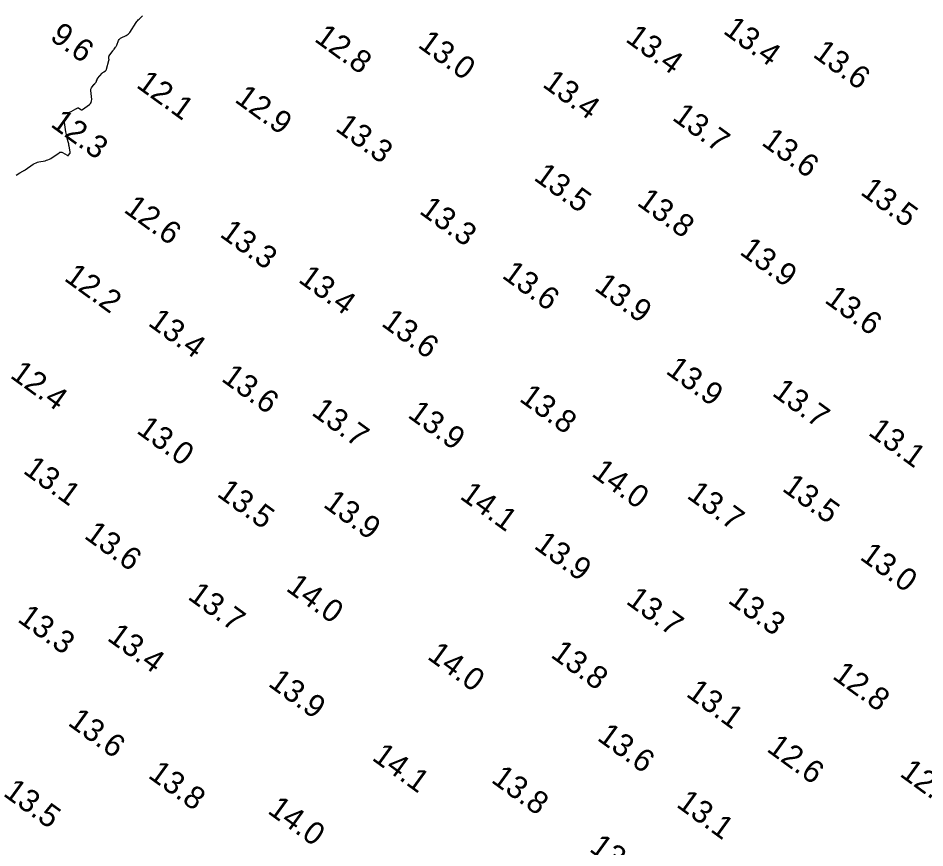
# Model space of a CAD drawing. Extents: x 815352 to 820877, y 582403 to 597439.
# Drawn here: x 817656.6 to 817857, y 585609.5 to 585793 of the extents above; entities that cross this region are included whole.
import ezdxf

# ---------------------------------------------------------------- set-up
doc = ezdxf.new("R2010")
doc.units = 0
doc.layers.add('V-CONT-EL12', color=7, linetype='Continuous')
doc.layers.add('V-TOPO-SOUN', color=7, linetype='Continuous')

msp = doc.modelspace()

# ---------------------------------------------------------------- linework, layer by layer
at = {"layer": 'V-CONT-EL12'}
msp.add_lwpolyline([(817656.1, 585758.28), (817656.92, 585758.79), (817657.02, 585758.85), (817657.12, 585758.91), (817657.22, 585758.97), (817657.32, 585759.03), (817657.73, 585759.25), (817657.83, 585759.31), (817657.94, 585759.37), (817658.03, 585759.44), (817658.13, 585759.5), (817659.93, 585760.73), (817660.22, 585760.91), (817660.53, 585761.06), (817660.84, 585761.17), (817661.17, 585761.25), (817662.52, 585761.51), (817662.85, 585761.59), (817663.17, 585761.7), (817663.48, 585761.84), (817663.77, 585762.02), (817665.63, 585763.27), (817665.82, 585763.37), (817666.02, 585763.41), (817666.21, 585763.38), (817666.41, 585763.29), (817667.44, 585762.7), (817667.52, 585762.66), (817667.6, 585762.66), (817667.68, 585762.69), (817667.74, 585762.76), (817668, 585763.08), (817668.05, 585763.17), (817668.08, 585763.26), (817668.1, 585763.36), (817668.09, 585763.46), (817667.86, 585764.72), (817667.81, 585764.96), (817667.76, 585765.21), (817667.7, 585765.45), (817667.64, 585765.69), (817667.36, 585766.79), (817667.29, 585767.06), (817667.23, 585767.32), (817667.18, 585767.59), (817667.14, 585767.86), (817666.82, 585769.95), (817666.8, 585770.21), (817666.83, 585770.45), (817666.91, 585770.69), (817667.03, 585770.91), (817667.68, 585771.88), (817667.8, 585772.04), (817667.94, 585772.18), (817668.1, 585772.31), (817668.27, 585772.41), (817669.33, 585772.98), (817669.34, 585772.98), (817669.35, 585772.99), (817669.36, 585773), (817669.38, 585773.01), (817669.42, 585773.04), (817669.43, 585773.05), (817669.44, 585773.06), (817669.45, 585773.07), (817669.46, 585773.07), (817669.74, 585773.18), (817669.79, 585773.19), (817669.84, 585773.19), (817669.89, 585773.18), (817669.94, 585773.16), (817670.42, 585772.81), (817670.52, 585772.76), (817670.61, 585772.74), (817670.71, 585772.76), (817670.8, 585772.81), (817672.33, 585773.92), (817672.58, 585774.15), (817672.74, 585774.41), (817672.82, 585774.71), (817672.83, 585775.05), (817672.62, 585777), (817672.62, 585777.18), (817672.65, 585777.34), (817672.71, 585777.5), (817672.81, 585777.65), (817673.41, 585778.4), (817673.46, 585778.46), (817673.5, 585778.52), (817673.55, 585778.58), (817673.6, 585778.64), (817673.79, 585778.89), (817673.83, 585778.95), (817673.87, 585779.01), (817673.9, 585779.07), (817673.93, 585779.14), (817674.01, 585779.41), (817674.04, 585779.47), (817674.07, 585779.54), (817674.11, 585779.6), (817674.15, 585779.65), (817675.18, 585780.87), (817675.25, 585780.95), (817675.33, 585781.03), (817675.42, 585781.1), (817675.51, 585781.17), (817675.87, 585781.41), (817675.96, 585781.48), (817676.03, 585781.56), (817676.08, 585781.65), (817676.11, 585781.75), (817676.62, 585783.63), (817676.64, 585783.72), (817676.66, 585783.81), (817676.66, 585783.9), (817676.65, 585783.99), (817676.62, 585784.35), (817676.62, 585784.44), (817676.63, 585784.52), (817676.66, 585784.6), (817676.71, 585784.68), (817677.5, 585785.78), (817677.58, 585785.89), (817677.65, 585785.99), (817677.73, 585786.09), (817677.81, 585786.19), (817678.12, 585786.59), (817678.2, 585786.69), (817678.26, 585786.8), (817678.32, 585786.91), (817678.38, 585787.03), (817678.79, 585788.07), (817678.89, 585788.27), (817679.03, 585788.44), (817679.19, 585788.58), (817679.38, 585788.69), (817680.47, 585789.2), (817680.71, 585789.33), (817680.92, 585789.49), (817681.11, 585789.68), (817681.27, 585789.89), (817682.67, 585792.05), (817682.81, 585792.25), (817682.96, 585792.45), (817683.12, 585792.63), (817683.3, 585792.8), (817684.06, 585793.51)], dxfattribs=at)

# ---------------------------------------------------------------- texts
at = {"layer": 'V-TOPO-SOUN'}
for s, p in [('9.6', (817663.38, 585788.41)), ('12.8 ', (817721.83, 585788.1)), ('13.4 ', (817812.22, 585789.84)), ('13.0 ', (817744.73, 585786.77)), ('13.4 ', (817790.63, 585788.03)), ('13.6 ', (817832.04, 585784.65)), ('13.4 ', (817772.26, 585778.03)), ('12.1 ', (817682.48, 585777.89)), ('12.9 ', (817704.21, 585774.68)), ('13.7 ', (817800.96, 585770.68)), ('12.3 ', (817663.53, 585769.24)), ('13.3 ', (817726.49, 585768.32)), ('13.6 ', (817820.69, 585765.16)), ('13.5 ', (817770.34, 585757.42)), ('13.5 ', (817842.55, 585754.21)), ('12.6 ', (817679.71, 585750.3)), ('13.3 ', (817745.03, 585750.01)), ('13.8 ', (817793.16, 585751.85)), ('13.3 ', (817700.93, 585744.89)), ('13.9 ', (817815.86, 585740.99)), ('12.2 ', (817666.52, 585735.18)), ('13.4 ', (817718.29, 585734.85)), ('13.6 ', (817763.31, 585735.77)), ('13.9 ', (817783.74, 585733.05)), ('13.6 ', (817834.63, 585730.32)), ('13.4 ', (817685.08, 585725.24)), ('13.6 ', (817736.64, 585725.17)), ('13.9 ', (817799.52, 585714.64)), ('12.4 ', (817654.57, 585713.69)), ('13.6 ', (817701.27, 585712.96)), ('13.8 ', (817767.14, 585708.51)), ('13.7 ', (817823.04, 585709.75)), ('13.7 ', (817721.21, 585705.46)), ('13.9 ', (817742.47, 585704.93)), ('13.0 ', (817682.53, 585701.46)), ('13.1 ', (817844.29, 585701.02)), ('13.1 ', (817657.45, 585692.59)), ('14.0 ', (817783.12, 585691.95)), ('13.5 ', (817825.26, 585688.66)), ('13.5 ', (817700.3, 585687.48)), ('14.1 ', (817754, 585686.94)), ('13.7 ', (817804.18, 585687.08)), ('13.9 ', (817723.8, 585685.11)), ('13.6 ', (817670.95, 585678.19)), ('13.9 ', (817770.39, 585675.96)), ('13.0 ', (817842.44, 585673.51)), ('14.0 ', (817715.57, 585666.59)), ('13.7 ', (817693.84, 585664.74)), ('13.3 ', (817813.27, 585663.92)), ('13.7 ', (817790.73, 585663.72)), ('13.3 ', (817656.21, 585659.75)), ('13.4 ', (817676.03, 585655.62)), ('13.8 ', (817774.09, 585651.88)), ('14.0 ', (817746.8, 585651.5)), ('12.8 ', (817836.36, 585647.16)), ('13.9 ', (817711.63, 585645.51)), ('13.1 ', (817804.03, 585643.24)), ('13.6 ', (817667.34, 585636.85)), ('13.6 ', (817784.37, 585633.53)), ('12.6 ', (817821.84, 585631.07)), ('14.1 ', (817734.58, 585629.13)), ('13.8 ', (817685.08, 585625.24)), ('13.8 ', (817760.94, 585624.22)), ('12.3 ', (817851.26, 585625.57)), ('13.5 ', (817653.05, 585621.24)), ('13.1 ', (817801.87, 585618.8)), ('14.0 ', (817711.5, 585617.38)), ('13.3 ', (817782.62, 585608.97))]:
    msp.add_text(s, height=5, rotation=324, dxfattribs=at).set_placement(p)

doc.saveas('drawing.dxf')
